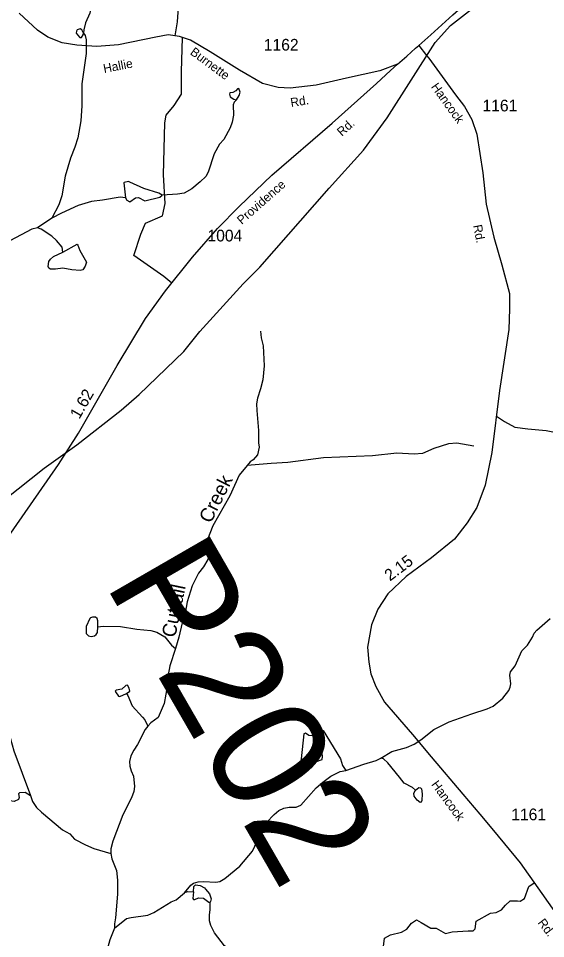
# Model space of a CAD drawing. Extents: x 2056842 to 2160602, y 826753 to 1016856.
# Drawn here: x 2103871 to 2109514, y 912699 to 922545 of the extents above; entities that cross this region are included whole.
import ezdxf

# ---------------------------------------------------------------- set-up
doc = ezdxf.new("R2010")
doc.units = 0
for name, color, linetype in [('Exist Hydrographic Creek Single Shore', 7, 'Continuous'), ('Exist Hydrographic Creek Single Shore Label', 7, 'Continuous'), ('Exist Hydrographic Misc Water Feature', 7, 'Continuous'), ('Exist Hydrographic Pond Under 1500 Sq Ft', 7, 'Continuous'), ('Exist Railroad Mainline', 7, 'Continuous'), ('Exist Road Non-System Type 51', 7, 'Continuous'), ('Exist Road Secondary Mileage Hundredths English Label', 7, 'Continuous'), ('Exist Road Secondary Structure Pipe Number Label', 7, 'Continuous'), ('Exist Road Secondary Type 51 Attributed', 7, 'Continuous'), ('Exist Road Secondary Type 51 Label', 7, 'Continuous'), ('Exist Road Secondary Type 51 Number Label', 7, 'Continuous')]:
    doc.layers.add(name, color=color, linetype=linetype)

msp = doc.modelspace()

# ---------------------------------------------------------------- linework, layer by layer
at = {"layer": 'Exist Hydrographic Creek Single Shore'}
for points in [[(2106462.7, 919198.5), (2106470.8, 919126.5), (2106491, 919042.4), (2106500, 918826.7), (2106488.4, 918678.6), (2106460.4, 918582.4), (2106430.8, 918482.3), (2106421, 918422.4), (2106421.2, 918350.5), (2106442, 918136.5), (2106440.5, 918002.3), (2106446.5, 917956.6), (2106430.7, 917876.5), (2106383, 917822.4), (2106351, 917800.1), (2106321, 917762)], [(2106321, 917762), (2106233.6, 917657.8), (2106134.1, 917435.5), (2105951.3, 917115.1), (2105895.8, 916970.9), (2105908.1, 916819), (2105898.5, 916754.9), (2105852.7, 916678.8), (2105798.8, 916610.7), (2105731.2, 916472.3), (2105675.9, 916304.1), (2105656.3, 916180.2), (2105624.6, 916076.2), (2105589, 915924), (2105551.4, 915804)], [(2105551.4, 915804), (2105492, 915617.9), (2105472.3, 915519.9), (2105466.5, 915415.6), (2105429.2, 915215.6), (2105365.7, 915063.4), (2105288.1, 915007.2), (2105256.2, 914971.1)], [(2105256.2, 914971.1), (2105226.2, 914935), (2105146.8, 914776.9), (2105106.8, 914714.7), (2105075, 914654.7), (2105059.3, 914592.6), (2105063.3, 914544.7), (2105077.6, 914494.5), (2105101.7, 914438.5), (2105114.2, 914326.7), (2105106.2, 914274.7), (2105080.5, 914206.7), (2104989.1, 914022.5), (2104879.9, 913741.9), (2104860.2, 913660), (2104860.5, 913610.1)], [(2104860.5, 913610.1), (2104870.4, 913554.1), (2104919, 913426.1), (2104931.3, 913326.1), (2104931.8, 913174.2), (2104910.5, 912922.3), (2104898.7, 912858.3), (2104901, 912810.3)], [(2104901, 912810.3), (2104849.2, 912686), (2104829.5, 912606.1), (2104759.9, 912493.7), (2104684.4, 912301.6), (2104645.3, 912031.4), (2104619.9, 911885.3), (2104606.2, 911713.3), (2104568.8, 911587.4), (2104548.9, 911559.3), (2104477.1, 911499.1), (2104449.1, 911460.9)]]:
    msp.add_lwpolyline(points, dxfattribs=at)
at = {"layer": 'Exist Hydrographic Misc Water Feature'}
for points in [[(2104742, 923304.5), (2104750.3, 923244.6), (2104736.9, 923088.7), (2104697.3, 922952.4), (2104677.4, 922908.5), (2104671.3, 922868.3), (2104673.5, 922772.4), (2104634.2, 922600.3), (2104588.7, 922496.3), (2104570.8, 922424.1), (2104568.8, 922388.1)], [(2104568.8, 922388.1), (2104585, 922364.1), (2104595.2, 922316.3), (2104595.7, 922168.3), (2104548.7, 921846.1), (2104549.4, 921610.2), (2104537.8, 921450.3), (2104508.4, 921266.2), (2104474.8, 921166.1), (2104429.1, 921050), (2104369.7, 920857.6), (2104334.4, 920645.7), (2104304.6, 920551.5), (2104229.1, 920407.4)], [(2106205, 921675.6), (2106179.4, 921649.4), (2106169.3, 921621.5), (2106173.6, 921509.4), (2106159.9, 921433.4), (2106137.9, 921373.3), (2106068.6, 921249.2), (2106022.5, 921198.9), (2105965.1, 921096.8), (2105903.6, 920898.6), (2105877.7, 920852.6), (2105818, 920796.4), (2105726.2, 920720.1), (2105644.4, 920675.9), (2105574.2, 920663.7), (2105408.6, 920653.2)], [(2105062, 920792), (2105050.1, 920800), (2105001.9, 920789.9), (2104998, 920785.9), (2105016.5, 920625.9)], [(2105408.6, 920653.2), (2105374.3, 920677), (2105214.4, 920724.6), (2105062, 920792)], [(2105016.5, 920625.9), (2104960.5, 920633.7), (2104770.4, 920599.2), (2104652.7, 920584.8), (2104508.8, 920544.3), (2104333.1, 920461.8), (2104229.3, 920407.4)], [(2105016.5, 920625.9), (2105030.4, 920600), (2105062.8, 920584.1), (2105124.6, 920624.3), (2105156.6, 920628.4), (2105222.6, 920592.6), (2105384.6, 920631.1), (2105408.6, 920653.2)], [(2104229.1, 920407.4), (2104075.4, 920304.9)], [(2104075.4, 920304.9), (2104015.7, 920288.8), (2103724.1, 920137.6), (2103652.4, 920067.6), (2103638.4, 920025.6), (2103548.8, 919957.2), (2103506.8, 919941), (2103410.8, 919920.7), (2103378.8, 919908.6), (2103283.1, 919834.4), (2103223.3, 919786.1)], [(2104346.6, 920045.8), (2104338.4, 920097.8), (2104280, 920167.6), (2104228.1, 920215.5), (2104115.7, 920291.2), (2104075.5, 920305)], [(2104346.6, 920045.8), (2104500, 920128.4), (2104508.4, 920120.4), (2104528.3, 920062.4), (2104598.8, 919936.7), (2104586.7, 919894.6)], [(2104267, 919863.6), (2104213.1, 919861.4), (2104197.1, 919873.5), (2104189.1, 919889.4), (2104196.7, 919945.4), (2104212.7, 919969.5), (2104246.5, 919997.5), (2104346.6, 920045.8)], [(2104586.7, 919894.6), (2104559, 919856.6), (2104531.1, 919846.4), (2104441.1, 919856.2), (2104345, 919871.8), (2104267, 919863.6)], [(2108746.2, 917969.9), (2108564.3, 918001.3), (2108476.3, 917993.1), (2108318.5, 917944.6), (2108194.8, 917888.2), (2108106.8, 917881.9), (2107922.7, 917893.3), (2107660.9, 917866.4), (2107135.1, 917842.9), (2106755.3, 917793.6), (2106577.4, 917783.1), (2106321.2, 917762.3)], [(2104634.5, 916123.2), (2104597, 916037.1), (2104597, 915965.1), (2104603.3, 915957.1)], [(2104721, 916035.4), (2104720.8, 916099.5), (2104714.5, 916123.4), (2104694.6, 916139.4), (2104662.6, 916139.3), (2104642.5, 916133.2), (2104634.5, 916123.2)], [(2107748.7, 914631.1), (2107868.6, 914701.4), (2108026.3, 914745.7), (2108108.4, 914778.1), (2108178.2, 914824.3), (2108317.7, 914936.9), (2108483.4, 915017.1), (2108725.1, 915104), (2108886.9, 915156.4), (2108952.9, 915186.8), (2109056.7, 915273), (2109122.3, 915353.3), (2109136.2, 915389.1), (2109140.2, 915425.1), (2109132, 915517.2), (2109139.6, 915553.1), (2109189.5, 915617.3), (2109259.1, 915777.7), (2109320.8, 915839.7), (2109372.4, 915923.9), (2109392.3, 915967.8), (2109420.2, 916000.1), (2109563.9, 916124.4)], [(2104603.3, 915957.1), (2104621.4, 915937.1), (2104649.3, 915933.2), (2104685.3, 915939.4), (2104703.4, 915951.4), (2104717.1, 915975.4), (2104721, 916035.4)], [(2104721, 916035.4), (2104776.8, 916043.6), (2104964.8, 916038.2), (2105137.1, 916008.8), (2105289, 915995.2), (2105351.1, 915979.4), (2105437.3, 915929.7), (2105509.7, 915840), (2105551.5, 915804.1)], [(2102670.1, 915757.1), (2102720.3, 915701.2), (2102768.3, 915637.3), (2102850.5, 915555.6), (2102891.1, 915463.7), (2102915.3, 915365.8), (2102945.3, 915329.9), (2103115.7, 915228.4), (2103223.7, 915142.8), (2103322.2, 915085.2), (2103380, 915065.3), (2103532.3, 915031.8), (2103610.3, 915000), (2103740.7, 914914.5), (2103786.8, 914836.6), (2103823.3, 914708.7), (2104000.7, 914231.4)], [(2105027.2, 915320.5), (2105041.3, 915300.5), (2105087.7, 915190.7), (2105197.8, 915067.1), (2105224, 915039.2), (2105256.4, 914971.3)], [(2107072.4, 914869), (2107106, 914927), (2107134.1, 914925.2), (2107317, 914623.8), (2107339.3, 914549.8), (2107375.2, 914497.9)], [(2107072.4, 914869), (2106980.3, 914870.6), (2106942.3, 914898.5), (2106926.4, 914890.5), (2106897, 914622.5), (2106885.3, 914572.4)], [(2107127.1, 914647.1), (2107116.8, 914743.1), (2107090.4, 914835.1), (2107072.4, 914869)], [(2106885.3, 914572.4), (2106885.3, 914546.4), (2106897.2, 914538.4), (2107123, 914617.2), (2107127.1, 914647.1)], [(2107375.1, 914497.7), (2107566.9, 914566.2), (2107698.9, 914604.8), (2107748.7, 914631.1)], [(2108120, 914288.3), (2108089.8, 914316.3), (2107999.8, 914363.9), (2107951.6, 914425.8), (2107825.1, 914581.4), (2107779, 914621.3), (2107749, 914631.1)], [(2105647.4, 913190.5), (2105717.3, 913270.8), (2105745.3, 913290.9), (2105795.2, 913306.9), (2105851, 913311), (2105985.1, 913301.7), (2106027.3, 913311.6), (2106081.1, 913344), (2106240.6, 913474.2), (2106378.1, 913634.8), (2106493.3, 913889), (2106525.3, 913941.1), (2106608.7, 914025.4), (2106658.8, 914069.6), (2106710.6, 914095.8), (2106770.5, 914106), (2106844.7, 914106.1), (2106894.6, 914126.4), (2107058, 914313), (2107127.8, 914372.9), (2107213.4, 914437.4), (2107315.2, 914485.5), (2107375.1, 914497.7)], [(2108120, 914288.3), (2108157.9, 914314.4), (2108173.9, 914312.5), (2108186, 914300.6), (2108192.1, 914248.6)], [(2103870.7, 914249), (2103886.7, 914263), (2103942.6, 914267.2), (2104000.7, 914231.4)], [(2104000.7, 914231.4), (2104022.8, 914167.4), (2104065.1, 914103.6), (2104117.3, 914051.8), (2104341.9, 913864.5), (2104421.8, 913818.7), (2104472.1, 913764.9), (2104588.4, 913701.3), (2104676.3, 913663.6), (2104860.7, 913610.2)], [(2105743.8, 913199), (2105747.5, 913255), (2105765.6, 913273), (2105815.6, 913267.2), (2105863.6, 913241.3), (2105873.6, 913229.4)], [(2105873.6, 913229.4), (2105915.9, 913177.5), (2105933.9, 913125.5), (2105928.2, 913097.5), (2105922, 913089.5)], [(2104901, 912810.3), (2105026.5, 912914.7), (2105078.6, 912926.7), (2105256.3, 912951.3), (2105320.1, 912977.5), (2105505.9, 913092.1), (2105557.9, 913114.3), (2105647.4, 913190.5)], [(2105647.9, 913190.7), (2105685.8, 913202.8), (2105743.8, 913199)], [(2105743.8, 913199), (2105737.9, 913127), (2105744, 913119), (2105760, 913119), (2105799.8, 913137.1), (2105851.9, 913131.3), (2105910.1, 913089.5), (2105922, 913089.5)], [(2106650.6, 912262), (2106626.4, 912299.9), (2106542.1, 912407.5), (2106457.8, 912471.3), (2106397.7, 912503.1), (2106293.8, 912542.8), (2106139.6, 912572.3), (2106077.6, 912622), (2105971, 912761.8), (2105930.8, 912839.6), (2105916.5, 912889.6), (2105914.6, 912949.6), (2105922.2, 913009.6), (2105922, 913089.5)]]:
    msp.add_lwpolyline(points, dxfattribs=at)
at = {"layer": 'Exist Hydrographic Pond Under 1500 Sq Ft'}
for points in [[(2104490.8, 922410), (2104489, 922387.8), (2104522.9, 922344.1), (2104527.1, 922342)], [(2104568.8, 922388.1), (2104548.9, 922424.3), (2104530.6, 922432.2), (2104500.9, 922423.9), (2104490.8, 922410)], [(2104527.1, 922342), (2104547.2, 922342.3), (2104565.1, 922368.1), (2104568.8, 922388.1)], [(2106216.7, 921791.5), (2106198.8, 921769.2), (2106164.7, 921753.2), (2106134.7, 921749.2), (2106130.8, 921733.2)], [(2106205.1, 921675.3), (2106234.8, 921719.6), (2106244.8, 921755.5), (2106228.5, 921793.6), (2106216.7, 921791.5)], [(2106130.8, 921733.2), (2106138.8, 921707.1), (2106175, 921681.1), (2106205.1, 921675.3)], [(2105020.8, 915408.2), (2104977, 915368.1), (2104917, 915355.8), (2104905, 915345.9), (2104909.1, 915338)], [(2105026.8, 915320.4), (2105062.9, 915348.5), (2105056.6, 915380.5), (2105038.6, 915412.4), (2105020.8, 915408.2)], [(2104909.1, 915338), (2104942.9, 915292), (2104955, 915288.1), (2105026.8, 915320.4)], [(2103870.3, 914248.8), (2103878.7, 914208.9), (2103870.7, 914188.8), (2103826.6, 914164.7), (2103778.9, 914172.6)], [(2108138.3, 914180.3), (2108106.1, 914224), (2108101.8, 914256.2), (2108119.9, 914288)], [(2108191.9, 914248.5), (2108190, 914176.3), (2108182.2, 914160.4), (2108170.3, 914156.4), (2108138.3, 914180.3)]]:
    msp.add_lwpolyline(points, dxfattribs=at)
at = {"layer": 'Exist Railroad Mainline'}
msp.add_lwpolyline([(2099514.5, 911843.1), (2099985.4, 912770.4), (2100363.3, 913475.7), (2101055.2, 914795.7), (2101387.3, 915392.7), (2101664.1, 915761.6), (2101749.9, 915827.8), (2101825.6, 915916), (2101927.3, 916010.3), (2103587.1, 917289.4), (2104147.7, 917731.1), (2104494.8, 917984.1), (2104969.8, 918353.5), (2105163.1, 918522.1), (2105641.7, 918981.6), (2105813.1, 919194.1), (2106277.3, 919703.5), (2106454.9, 919884), (2107198.1, 920728.3), (2107564.8, 921135.4), (2107819.8, 921480.1), (2108331.2, 922285.8), (2108494.6, 922468.2), (2108751.8, 922670.9)], dxfattribs=at)
at = {"layer": 'Exist Road Non-System Type 51'}
for points in [[(2105612.5, 923236.1), (2105599.1, 922927.8), (2105571.2, 922508.1), (2105545.9, 922359)], [(2105513, 919714.1), (2105427.5, 919782.9), (2105107.8, 920009.4), (2105179.6, 920235.9), (2105229.9, 920354.5), (2105413.1, 920433.6), (2105441.9, 920563.1), (2105423.9, 920872.3), (2105436.5, 921427.7), (2105450.9, 921510.4), (2105537.1, 921614.7), (2105616.1, 921733.3), (2105616.1, 921974.2), (2105625.9, 922341.1)], [(2108987.3, 918288.1), (2109072.7, 918231.1), (2109185.9, 918170), (2109324.2, 918152), (2109520, 918135.9), (2109717.6, 918098.1), (2109895.4, 918098.1), (2110116.4, 918065.8), (2110384.9, 918052.3)], [(2107777.5, 912615.5), (2107789.2, 912704.5), (2107852.1, 912740.4), (2107972.4, 912767.4), (2108027.2, 912798.8), (2108079.3, 912863.5), (2108133.2, 912899.5), (2108183.5, 912872.5), (2108285.9, 912809.6), (2108343.4, 912811.4), (2108442.2, 912753.9), (2108514, 912771.9), (2108686.5, 912780.9), (2108738.6, 912782.7), (2108761.9, 912804.2), (2108769.1, 912886.9), (2108922.7, 912970.5), (2108985.6, 912979.5), (2109041.3, 913008.3), (2109084.4, 913056.8), (2109134.7, 913101.7), (2109211.9, 913101.7), (2109242.5, 913098.1), (2109287.4, 913128.7), (2109335.9, 913258.1), (2109392.5, 913297.2)]]:
    msp.add_lwpolyline(points, dxfattribs=at)
at = {"layer": 'Exist Road Secondary Type 51 Attributed'}
for points in [[(2108157.9, 922255.2), (2108284.9, 922370.7), (2108520.2, 922582.7), (2108700.6, 922740), (2108934.1, 922901.7), (2109181.9, 923052.6), (2109664, 923350), (2109960.3, 923531.5), (2110469.4, 923830.7), (2110873.4, 924058.9), (2111077.2, 924176.6), (2111147.2, 924243.1), (2111246, 924404.8), (2111341.2, 924557.6), (2111627.6, 924957.4), (2111744.3, 925119.1)], [(2107929.8, 922054.9), (2107740.9, 921984.4), (2107383.5, 921905.3), (2107058.5, 921831.6), (2106781.1, 921798.4), (2106650, 921807.4), (2106483, 921848.7), (2106238.8, 921992.4), (2105921.8, 922187.4), (2105713.5, 922311.4), (2105596.8, 922350.9), (2105472.9, 922370.7), (2105341.8, 922345.5), (2104940.5, 922262), (2104708.9, 922244), (2104495.2, 922260.2), (2104338.9, 922285.3), (2104187.2, 922343.7), (2104074.1, 922421), (2103880.2, 922600.7)], [(2107929.8, 922054.9), (2108030, 922142.5), (2108121.5, 922226), (2108157.9, 922255.2)], [(2108157.9, 922255.2), (2108240.6, 922149.9)], [(2108240.6, 922149.9), (2108263.4, 922120.9), (2108549.8, 921728.3), (2108646.8, 921602.5), (2108725.8, 921464.1), (2108779.6, 921306), (2108841.6, 920891.8), (2108879.3, 920557.6), (2108961, 920206.3), (2109047.2, 919909.8), (2109126.2, 919602.5), (2109128.9, 919436.3), (2109121.7, 919215.3), (2109022.1, 918563.9), (2108938.6, 917901.7), (2108868.5, 917551.3), (2108779.6, 917311.5), (2108673.7, 917147.9), (2108537.2, 916971.8), (2108292.1, 916775.1), (2108022.8, 916572), (2107827, 916388.7), (2107718.4, 916224.3), (2107650.2, 916055.4), (2107608.9, 915818.2), (2107622.3, 915655.6), (2107643.9, 915533.4), (2107697.8, 915396.8), (2107791.1, 915227.9), (2108090.1, 914882), (2108287.6, 914644.8), (2108629.7, 914243.2), (2108809.3, 914029.4), (2108956.5, 913855.1), (2109242.9, 913511), (2109431.5, 913241.4), (2109694.5, 912868.6)], [(2102659.1, 915413), (2104299.8, 917770.9), (2104512.7, 918107), (2104926.6, 918832.1), (2105231, 919332.6), (2105446.4, 919630.8), (2105734.6, 919991.1), (2106002.2, 920298.4), (2106234.7, 920531.1), (2106583.1, 920868.9), (2107228.6, 921425.1), (2107705.4, 921848.2), (2107854.4, 921988.4), (2107929.8, 922054.9)]]:
    msp.add_lwpolyline(points, dxfattribs=at)

# ---------------------------------------------------------------- texts
at = {"layer": 'Exist Hydrographic Creek Single Shore Label'}
for s, rotation, p in [('Creek', 63.44941, (2105929.4, 917133.6)), ('Cuttail', 78.47505, (2105549.4, 915913.7))]:
    msp.add_text(s, height=150, rotation=rotation, dxfattribs=at).set_placement(p)
at = {"layer": 'Exist Road Secondary Mileage Hundredths English Label'}
for s, rotation, p in [('1.62', 60.27996, (2104522.6, 918250.5)), ('2.15', 37.01103, (2107848, 916518.6))]:
    msp.add_text(s, height=125, rotation=rotation, dxfattribs=at).set_placement(p)
at = {"layer": 'Exist Road Secondary Structure Pipe Number Label'}
msp.add_text('P202', height=1230.31, rotation=300, dxfattribs=at).set_placement((2104784.8, 916506.1))
at = {"layer": 'Exist Road Secondary Type 51 Label'}
for s, rotation, p in [('Burnette', 323.50334, (2105701.2, 922167.5)), ('Hallie', 11.15535, (2104788.7, 921959.7)), ('Hancock', 305.77252, (2108283.5, 921812.8)), ('Rd.', 8.88785, (2106790.3, 921596.9)), ('Rd.', 41.82721, (2107332.9, 921278.5)), ('Providence', 41.34996, (2106261.8, 920334.6)), ('Rd.', 280.94103, (2108738.2, 920329.4)), ('Hancock', 306.26948, (2108285.9, 914347.8)), ('Rd.', 307.43378, (2109425.3, 912868.1))]:
    msp.add_text(s, height=95, rotation=rotation, dxfattribs=at).set_placement(p)
at = {"layer": 'Exist Road Secondary Type 51 Number Label'}
for s, p in [('1162', (2106498.1, 922201)), ('1161', (2108839.1, 921550.4)), ('1004', (2105894.8, 920159.1)), ('1161', (2109146.7, 913965.5))]:
    msp.add_text(s, height=125, dxfattribs=at).set_placement(p)

doc.saveas('drawing.dxf')
